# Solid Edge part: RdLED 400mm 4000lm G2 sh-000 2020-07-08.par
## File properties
Author: sylwester.cabaj
Template: iso metric part.par
Last saved by: sylwester.cabaj
Revision: 3
Application: Solid Edge
Gęstość: 0,000 kg/m^3
Dokładność: 0,990
Username: sylwester.cabaj
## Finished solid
Body 1: solid body, 3075 faces, 8002 edges, 5206 vertices.
  Faces by surface: plane 2567, cylinder 240, spline 160, cone 52, torus 22, sphere 20, spun 14
  Edges by curve: line 6900, curve on surface 564, circle 318, ellipse 132, spline 76, intersection 12
Bounding box of the edges (mm; curved faces can reach further): 390.000 x 4.450 x 390.000, from (-195, -3.45, -195) to (195, 1, 195).
Cylindrical faces by radius (mm): R0.2 x78, R0.2002 x4, R0.2169 x6, R0.25 x24, R0.3 x4, R0.3373 x6, R0.4 x16, R0.4006 x4, R0.4008 x4, R0.525 x4, R0.6 x24, R1 x16, R1.0894 x4, R1.1 x28, R2.15 x12, R2.5 x1, R5 x1, R200 x4
Conical faces (half-angle, radius in mm at the cone's reference point): 0.5 deg R0.5056 x8, 0.5 deg R1.0082 x8, 1 deg R0.5511 x4, 10 deg R0.2132 x4, 10 deg R0.4132 x4, 18.4844 deg R1.0657 x8, 27.363 deg R0.6214 x4, 45 deg R0.575 x4, 45 deg R0.625 x8
Toroidal faces (ring radius, tube radius in mm): R0.1 r0.2 x2, R0.8 r0.2 x8, R0.8522 r0.3 x4, R0.9002 r0.2 x2, R0.9018 r0.2 x2, R1.3 r0.2 x4
Spherical faces by radius (mm): R0.2 x16, R0.6 x4
Planar faces by outward normal: +x 43, +y 15, +z 42, -x 42, -y 459, -z 42, oblique 1924
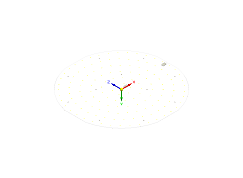
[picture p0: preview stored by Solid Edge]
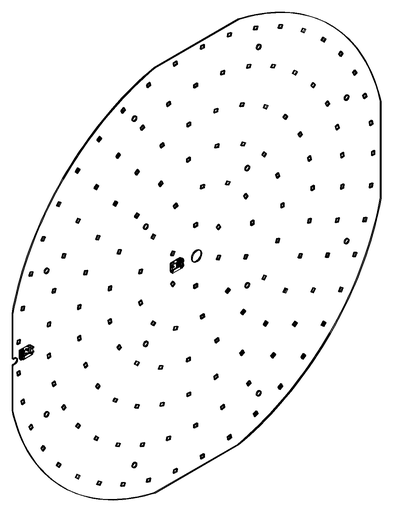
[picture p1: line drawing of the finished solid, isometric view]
